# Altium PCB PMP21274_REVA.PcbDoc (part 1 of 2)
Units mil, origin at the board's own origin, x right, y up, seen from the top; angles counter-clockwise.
Board outline 3250 x 2700 mil, 4 copper layers (Top Layer, Signal Layer 1, Signal Layer 2, Bottom Layer), stack 61.6 mil thick; 81 components, 30 nets, 178 pads, 45 vias.
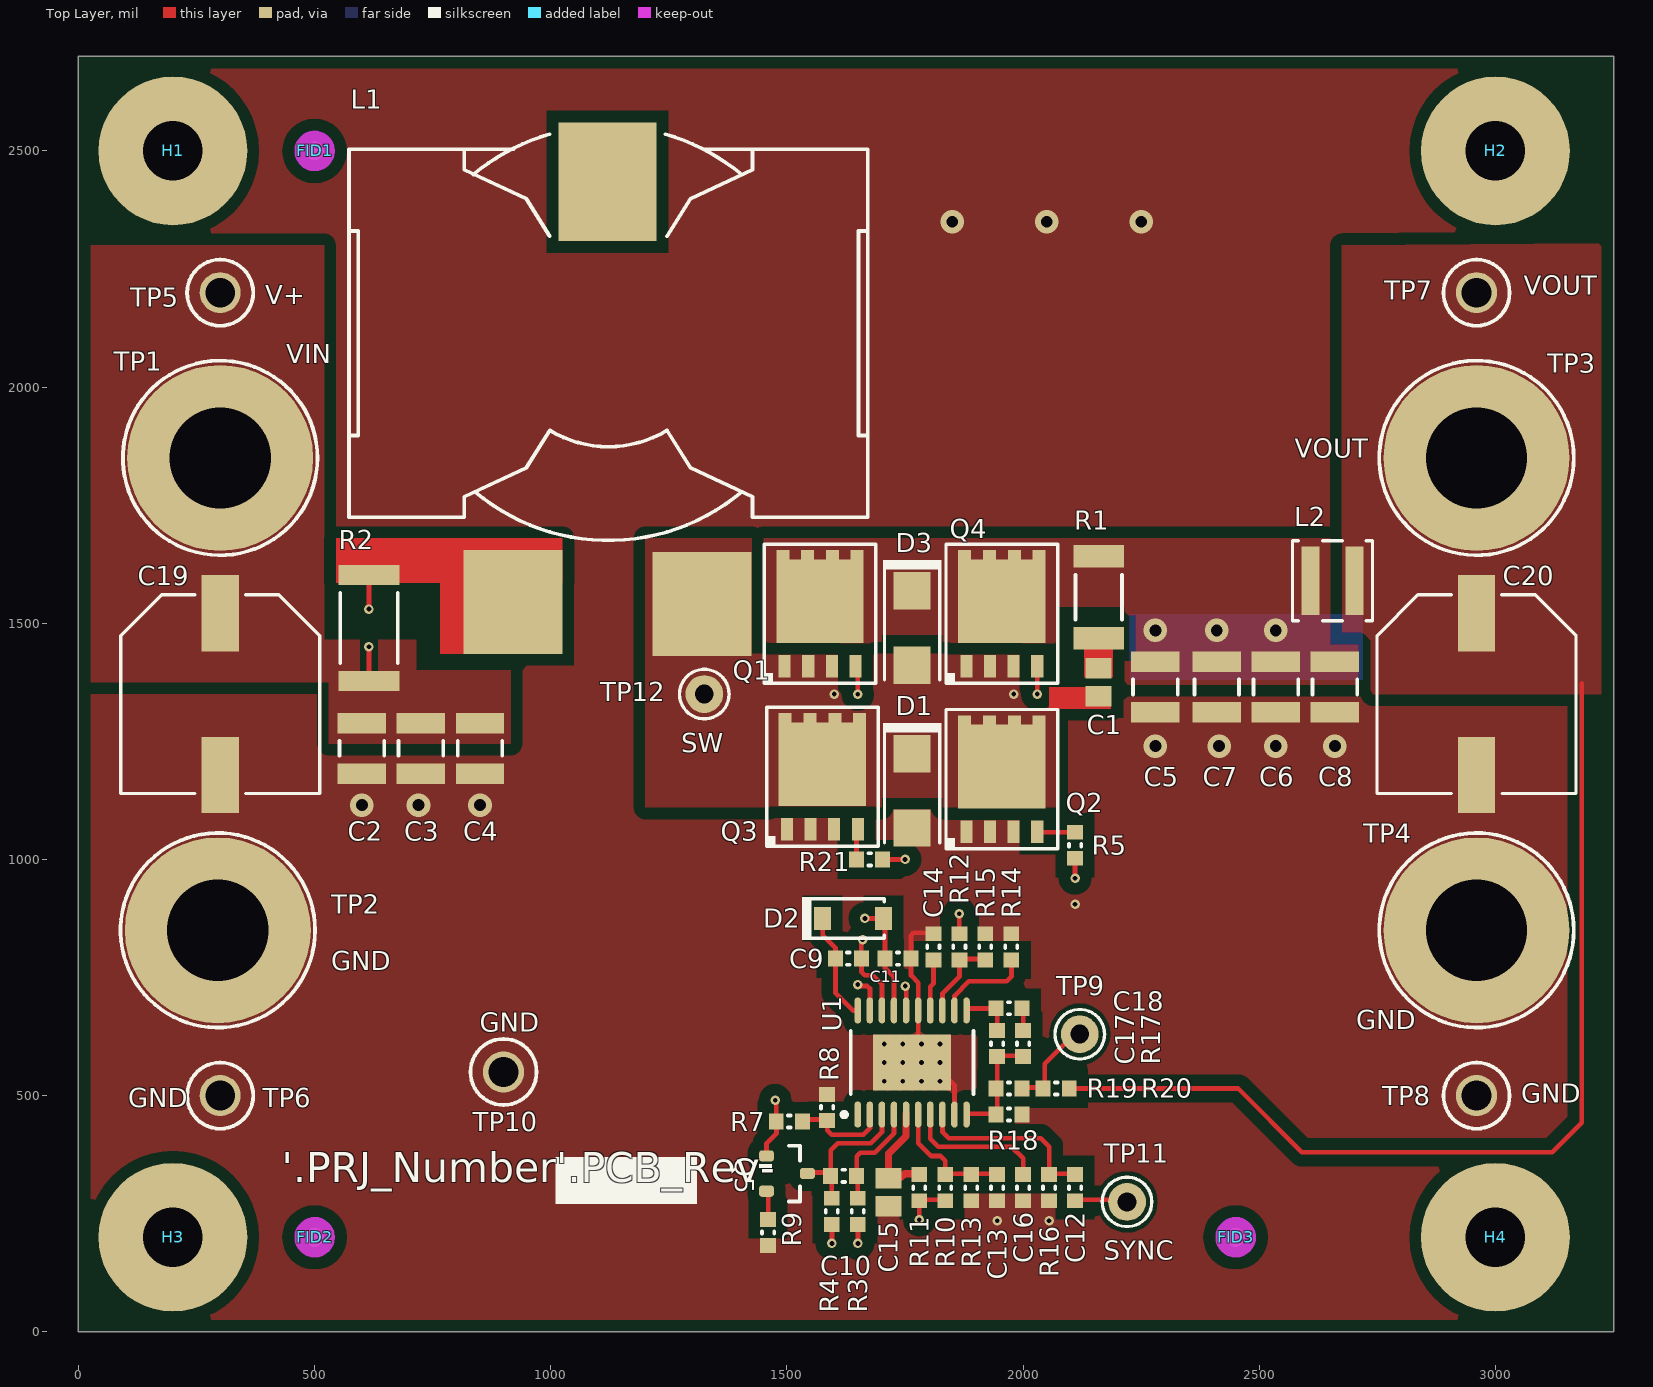
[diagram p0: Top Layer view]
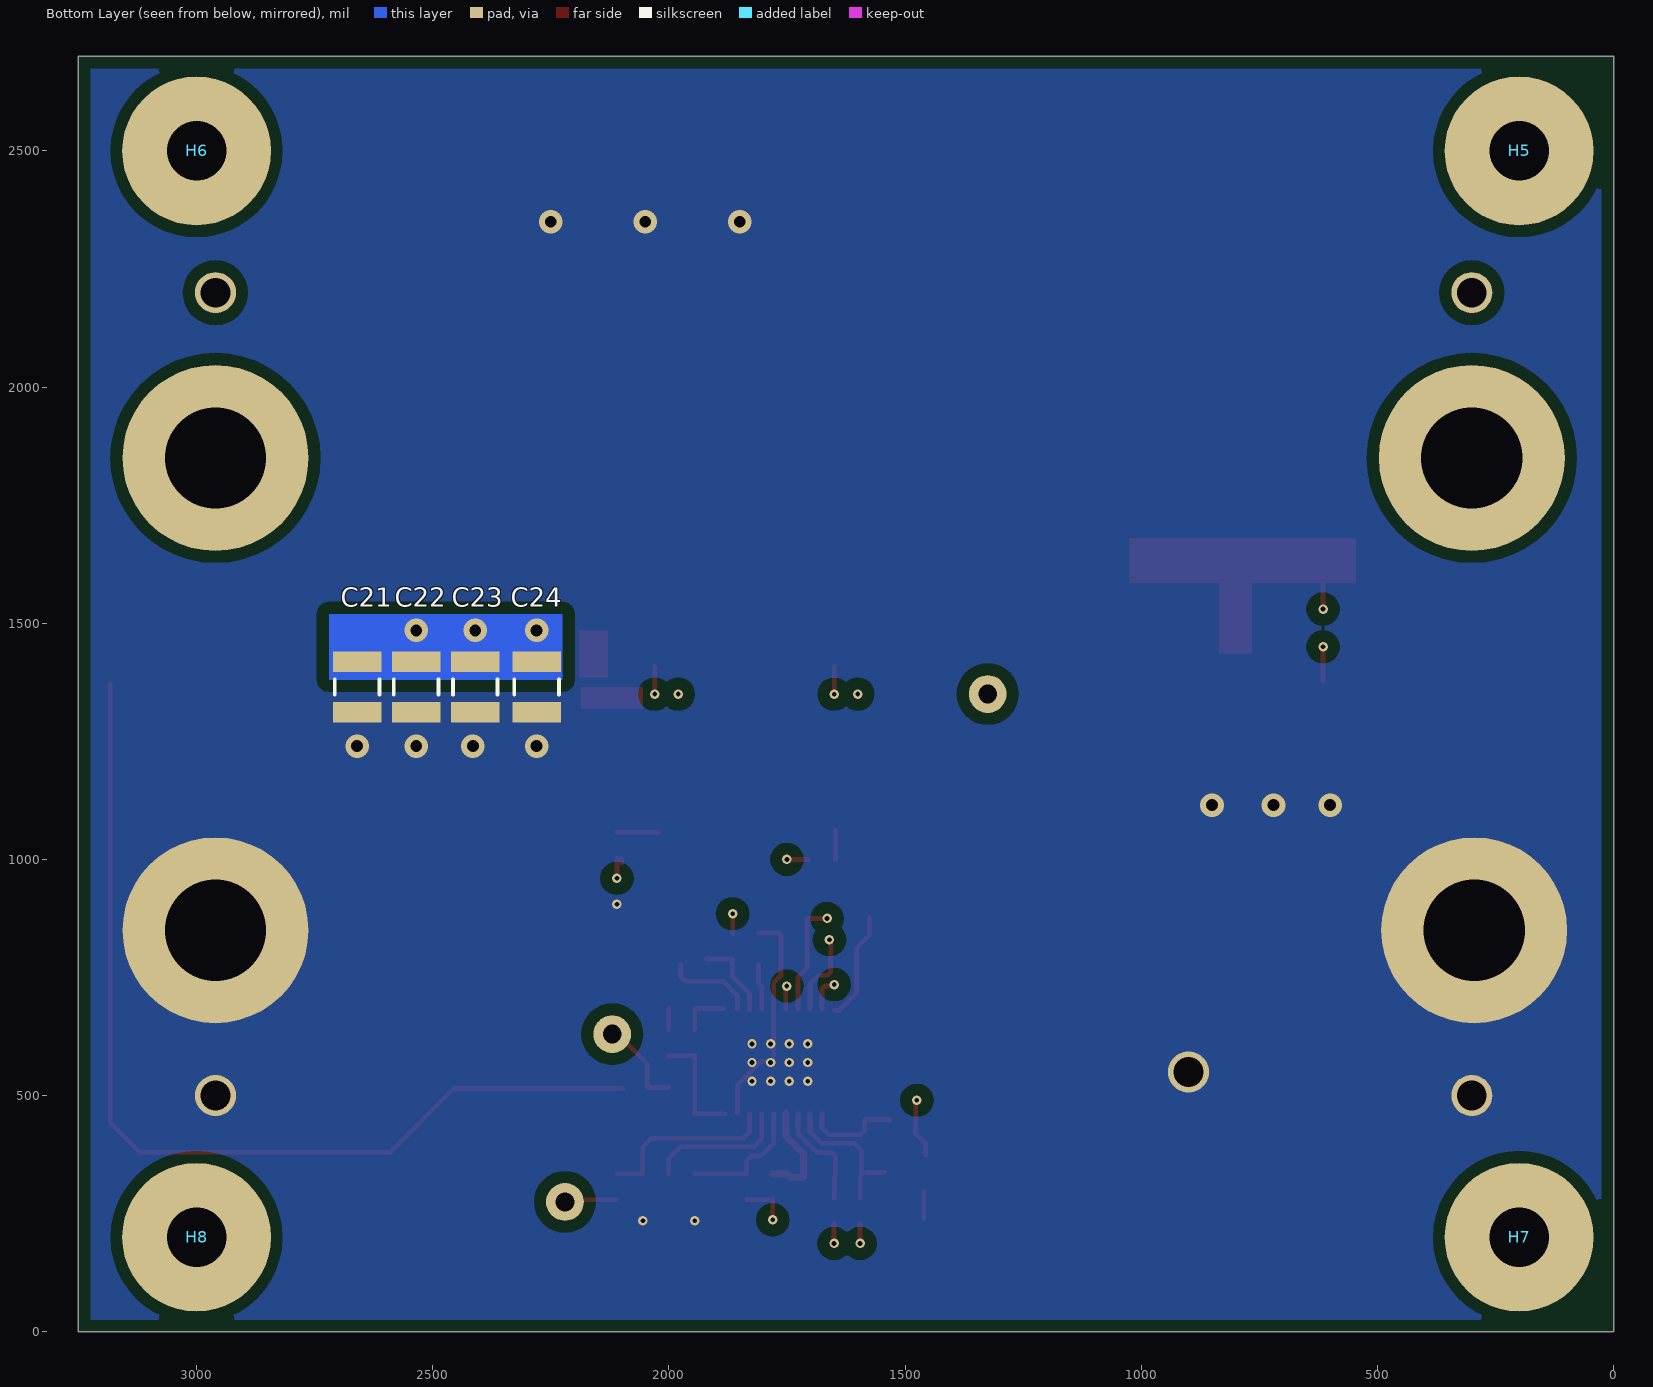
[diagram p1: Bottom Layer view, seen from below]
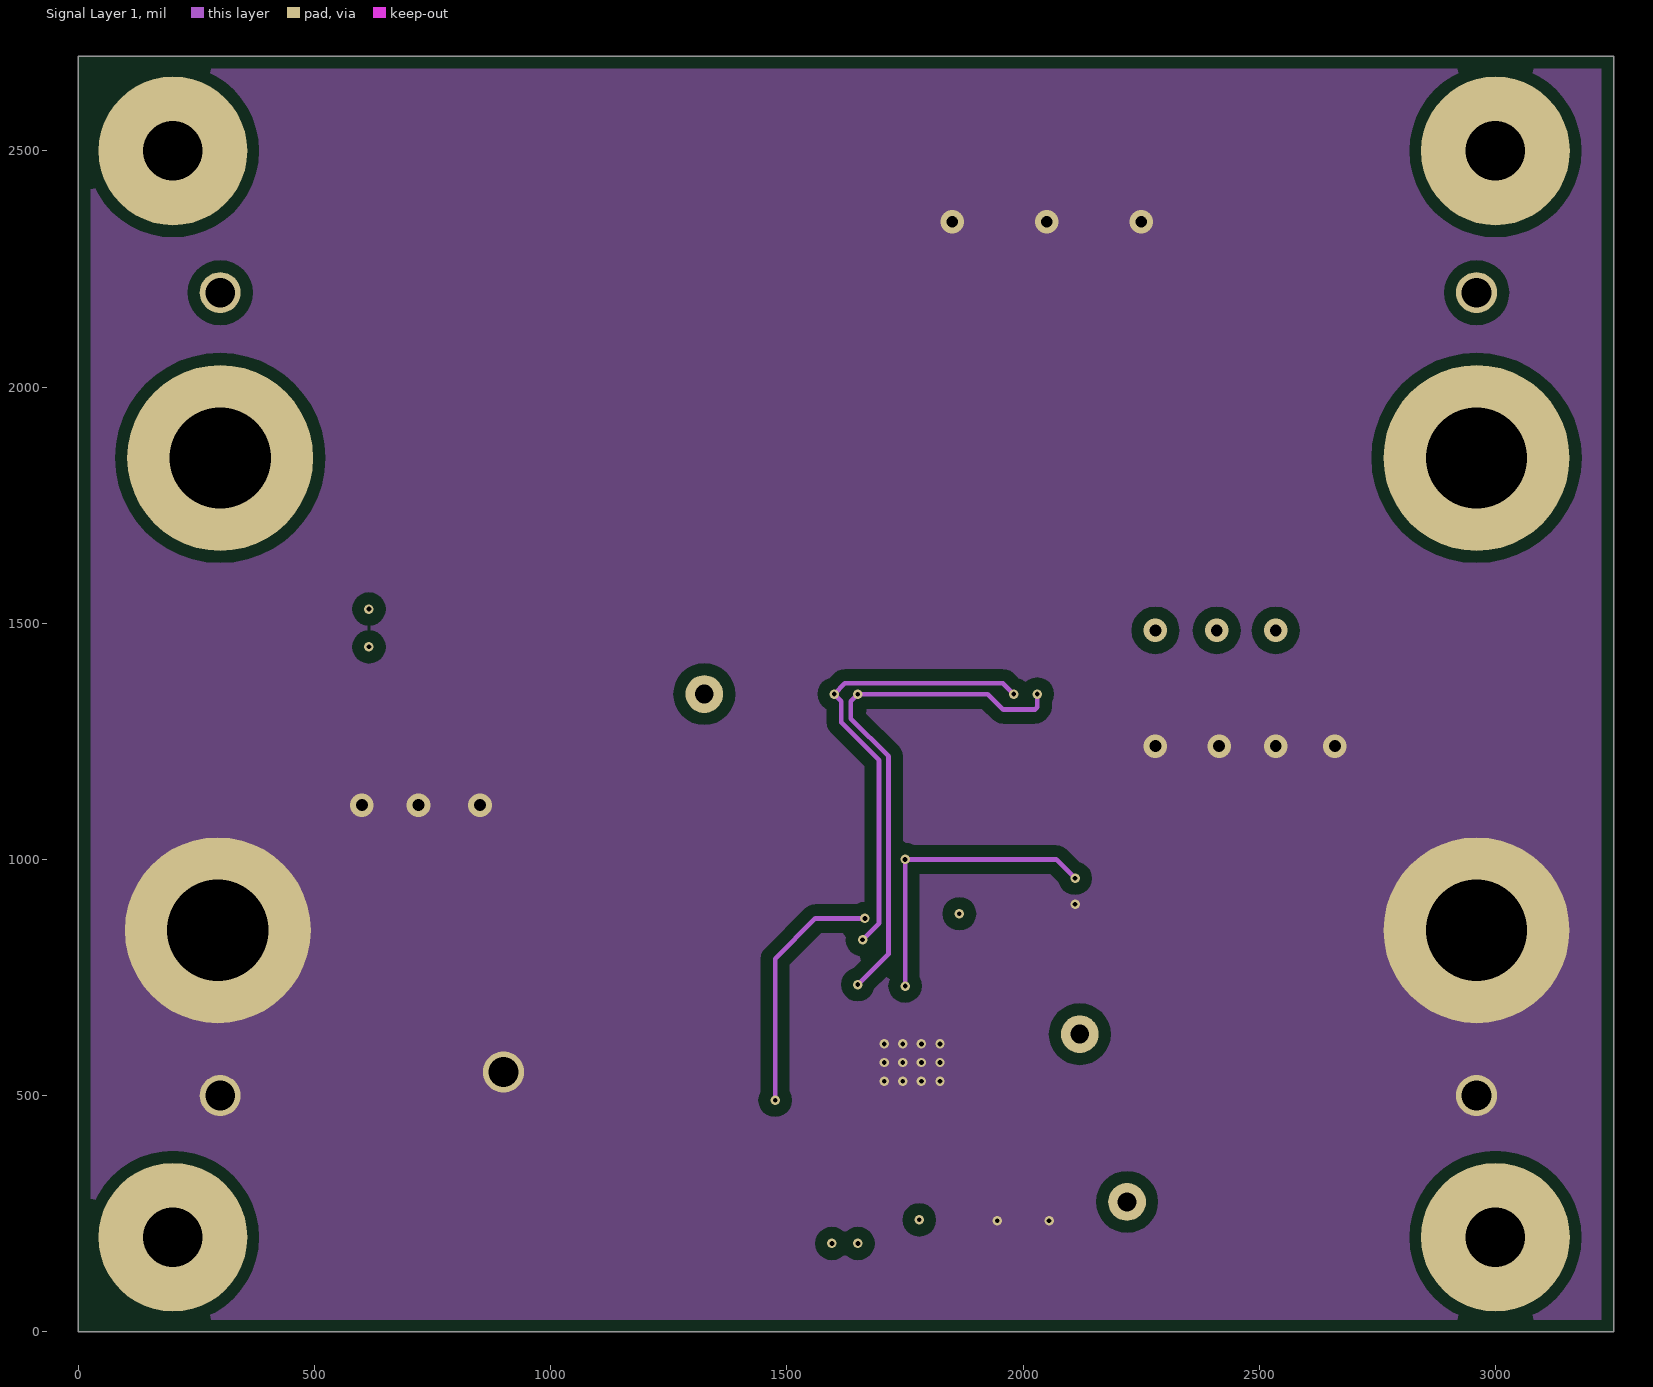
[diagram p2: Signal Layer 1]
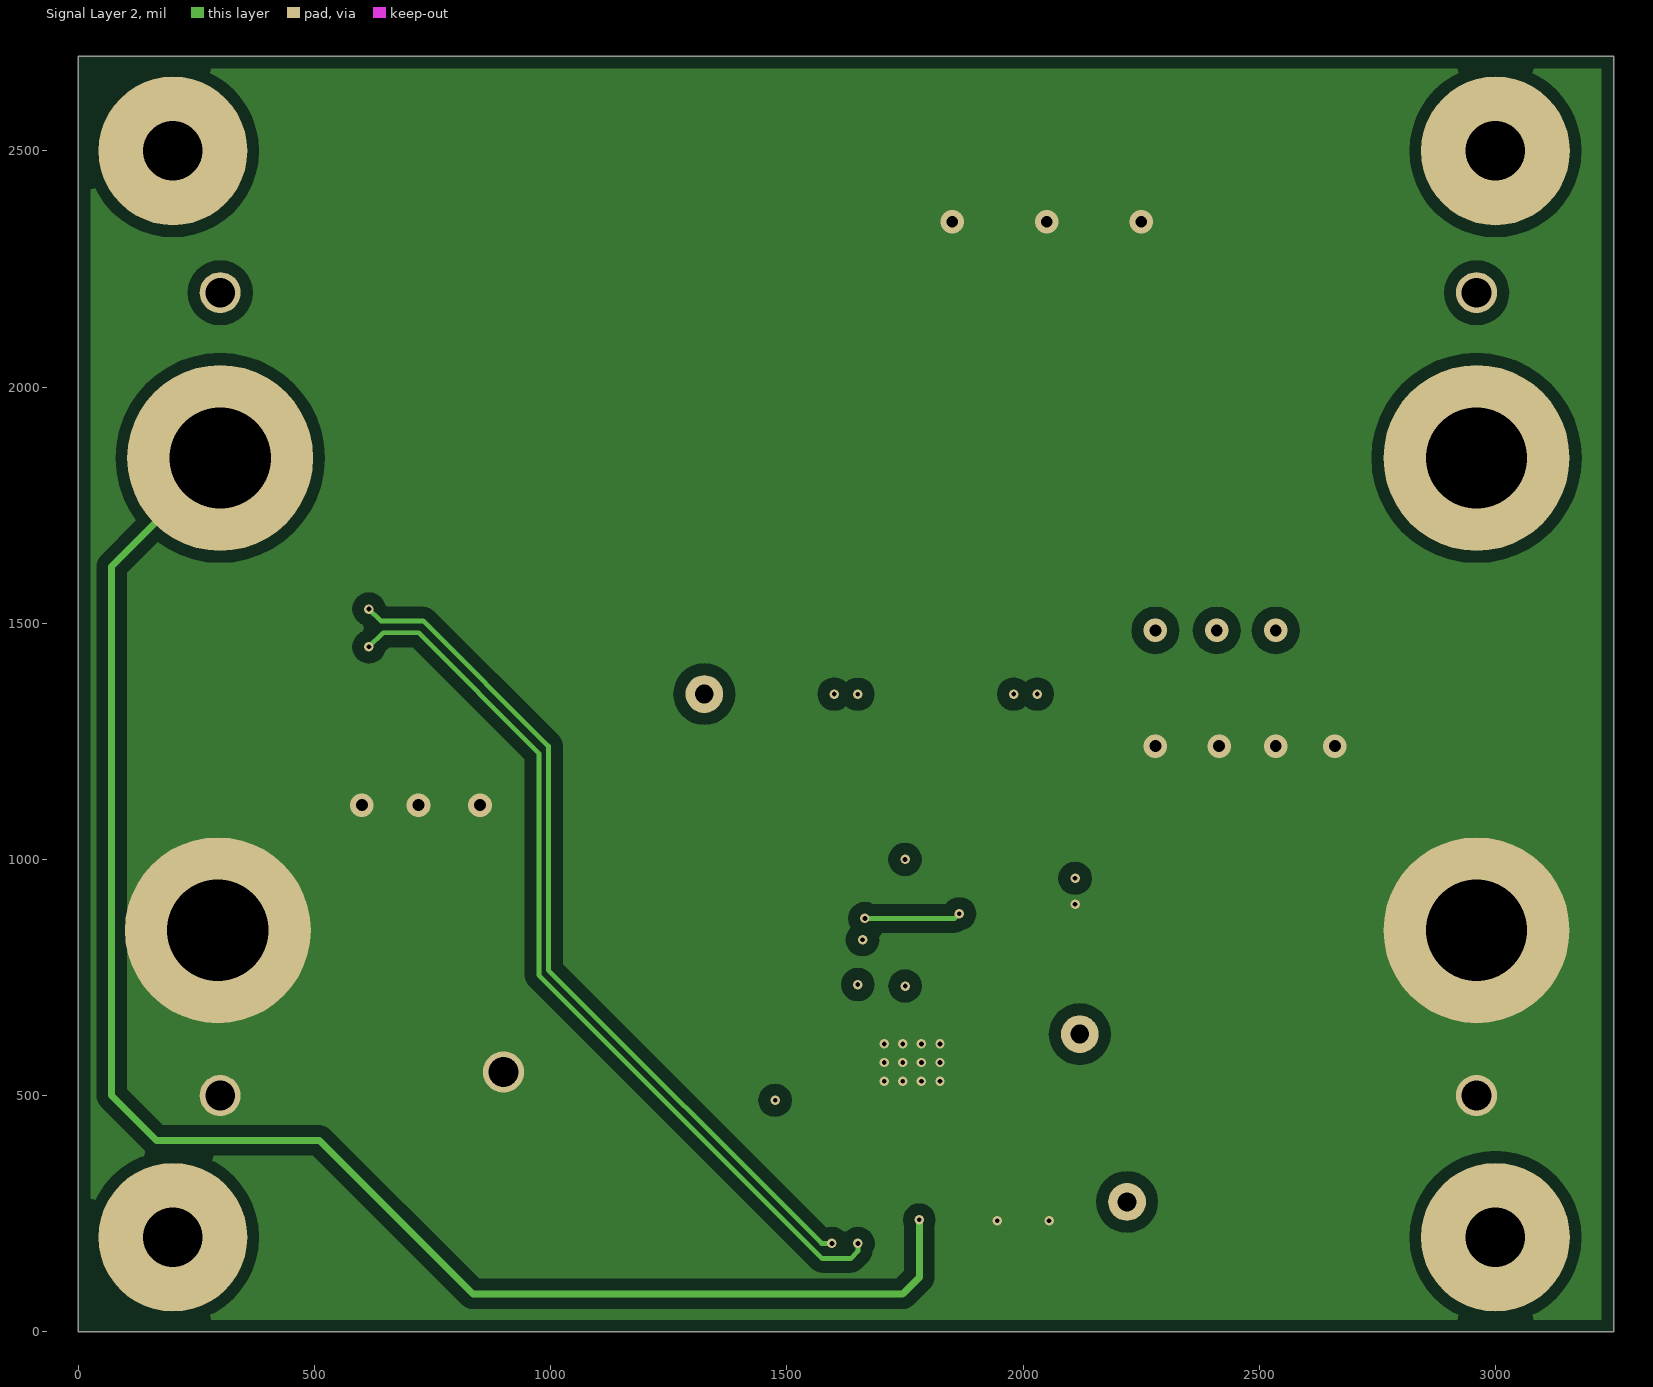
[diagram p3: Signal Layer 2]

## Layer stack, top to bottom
Top Solder: solder mask 0.4, Solder Resist, Dk 3.5
Top Layer: signal copper 1.4
Dielectric1: core 14, FR-4, Dk 4.2
Signal Layer 1: signal copper 1.4
Dielectric 2: core 28, Dk 4.2
Signal Layer 2: signal copper 1.4
Dielectric 3: core 14, Dk 4.2
Bottom Layer: signal copper 1.4
Bottom Solder: solder mask 0.4, Solder Resist, Dk 3.5

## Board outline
0,0 3250,0 3250,2700 0,2700

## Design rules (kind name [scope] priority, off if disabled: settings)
AcuteAngle [All] p1: minimum=4.50000000000000E+0001 checktracksonly=FALSE
AssemblyTestPointUsage [All] p1: valid=2
BoardOutlineClearance BoardOutlineClearance_MountingHoles [OnCopper and InComponentClass('Mounting Holes')] p1: gap=40 ignorepadtopadclearanceinfootprint=FALSE
BoardOutlineClearance BoardOutlineClearance_Poly [OnCopper and IsPoly] p2: gap=25 ignorepadtopadclearanceinfootprint=FALSE
BoardOutlineClearance [OnCopper and Not InComponentClass('Logo') and not InComponentClass('FiducialMark') and not InRegion(1000,500,4000,800) and not InPoly] p3: gap=49 ignorepadtopadclearanceinfootprint=FALSE
Clearance Clearance_Keepouts [((IsTrack Or IsArc) And Not InPoly) And IsFree and IsKeepOut vs ((IsTrack Or IsArc) And Not InPoly) And IsFree and IsKeepOut] p1: gap=0 ignorepadtopadclearanceinfootprint=FALSE
Clearance Clearance_Poly [InPolygon] p2: gap=25 ignorepadtopadclearanceinfootprint=FALSE except(0: Arc-Hole Track-Hole SMDPad-Hole THPad-Hole Via-Hole Fill-Hole Poly-Hole Region-Hole Text-Hole)
Clearance Clearance_FiducialMark [IsKeepOut and InComponentClass('FiducialMark') vs IsPad and InComponentClass('FiducialMark')] p3: gap=0 ignorepadtopadclearanceinfootprint=FALSE
Clearance [All] p4: gap=7.87 ignorepadtopadclearanceinfootprint=FALSE except(0: Arc-Hole Track-Hole SMDPad-Hole THPad-Hole Via-Hole Fill-Hole Poly-Hole Region-Hole Text-Hole)
ComponentClearance ComponentClearance_MountingHoles_FiducialMarks [InComponentClass('Mounting Holes') vs InComponentClass('FiducialMark')] p1: gap=50 collisioncheckmode=3 verticalgap=10 showdistances=FALSE
ComponentClearance ComponentClearance_Shunt [InComponentClass('Header') vs InComponentClass('Shunt')] p2: gap=0 collisioncheckmode=3 verticalgap=0 showdistances=FALSE
ComponentClearance ComponentClearance_Logo [InComponentClass('Logo')] p3: gap=50 collisioncheckmode=3 verticalgap=10 showdistances=FALSE
ComponentClearance ComponentClearance_ScrewToNut [(HasFootprint('NY PMS 440 0025 PH')) vs (HasFootprint('Keystone_1902C'))] p4: gap=5 collisioncheckmode=3 verticalgap=10 showdistances=FALSE
ComponentClearance ComponentClearance_MountingHoles [InComponentClass('Mounting Holes')] p5: gap=100 collisioncheckmode=3 verticalgap=100000 showdistances=FALSE
ComponentClearance ComponentClearance_SmallPassives [HasFootprint('0201*') or HasFootprint('0402*') or HasFootprint('0508') or HasFootprint('0603*') or HasFootprint('0612') or HasFootprint('0805*') or HasFootprint('0815*') or HasFootprint('0830*') or HasFootprint('1206*') or HasFootprint('1210*') or HasFootprint('1808*') or HasFootprint('1812*') or HasFootprint('1825*') or HasFootprint('2010*') or HasFootprint('2220*') or HasFootprint('2225*') or HasFootprint('2512*') or HasFootprint('2728*') or HasFootprint('3518*') vs HasFootprint('0201*') or HasFootprint('0402*') or HasFootprint('0508') or HasFootprint('0603*') or HasFootprint('0612') or HasFootprint('0805*') or HasFootprint('0815*') or HasFootprint('0830*') or HasFootprint('1206*') or HasFootprint('1210*') or HasFootprint('1808*') or HasFootprint('1812*') or HasFootprint('1825*') or HasFootprint('2010*') or HasFootprint('2220*') or HasFootprint('2225*') or HasFootprint('2512*') or HasFootprint('2728*') or HasFootprint('3518*')] p6: gap=14.96 collisioncheckmode=3 verticalgap=10 showdistances=FALSE
ComponentClearance ComponentClearance_THtoSMT [IsThruComponent vs IsSMTComponent] p7: gap=40 collisioncheckmode=3 verticalgap=30 showdistances=FALSE
ComponentClearance ComponentClearance_THtoTH [IsThruComponent vs IsThruComponent] p8: gap=30 collisioncheckmode=3 verticalgap=30 showdistances=FALSE
ComponentClearance [All] p9: gap=30 collisioncheckmode=3 verticalgap=10 showdistances=FALSE
DiffPairsRouting [All] p1: maxlimit=100 minlimit=10 mostfreqgap=10 toplayer_minwidth=10 toplayer_maxwidth=15 toplayer_prefwidth=15 midlayer1_minwidth=10 midlayer1_maxwidth=15 midlayer1_prefwidth=15 midlayer2_minwidth=10 midlayer2_maxwidth=15 midlayer2_prefwidth=15 bottomlayer_minwidth=10 bottomlayer_maxwidth=15 bottomlayer_prefwidth=15 maxuncoupledlength=1000
FabricationTestPointUsage TestPointUsage [All] p1: valid=2 allowmultiple=FALSE
FabricationTestpoint Testpoint [All] p1: side=3 testpointundercomponent=TRUE minsize=40 maxsize=100 preferedsize=60 minholesize=0 maxholesize=40 preferedholesize=32 testpointgrid=1 allowsidetop=TRUE allowsidebottom=TRUE usegrid=TRUE gridtolerance=0.01
FanoutControl Fanout_LCC [IsLCC] p1: bgadir=Out bgaviamode=Centered fanoutstyle=Auto fanoutdirection=Alternating viagrid=1 // Fanout_LCC (Default Rule)
FanoutControl Fanout_BGA [IsBGA] p2: bgadir=Out bgaviamode=Centered fanoutstyle=Auto fanoutdirection=Alternating viagrid=1 // Fanout_BGA (Default Rule)
FanoutControl Fanout_Default [All] p4: bgadir=Out bgaviamode=Centered fanoutstyle=Auto fanoutdirection=Alternating viagrid=1 // Fanout_Default (Default Rule)
FanoutControl Fanout_Small [(CompPinCount < 5)] p5: bgadir=Out bgaviamode=Centered fanoutstyle=Auto fanoutdirection=OutThenIn viagrid=1 // Fanout_Small (Default Rule)
HoleSize [All] p1: absolutevalues=TRUE maxlimit=251 minlimit=7.87 maxpercent=80.000 minpercent=20.000
MinimumAnnularRing MinimumAnnularRing_ThermalPadVias [IsVia and InAnyComponent] p1: minimumring=5
MinimumAnnularRing [All] p2: minimumring=5
MinimumSolderMaskSliver MinimumSolderMaskSliver_Logo [InComponentClass('Logo') vs InComponentClass('Logo')] p1: minsoldermaskwidth=0.7
MinimumSolderMaskSliver [All] p2: minsoldermaskwidth=3.94
PlaneConnect [All] p1: planeconnectstyle=Direct reliefexpansion=10 reliefentries=4 reliefconductorwidth=10 reliefairgap=10
PolygonConnect [All] p1: connectstyle=Direct reliefconductorwidth=10 reliefentries=4 polygonreliefangle="90 Angle" airgapwidth=10
RoutingVias ThermalPadVias [IsVia and InAnyComponent] p1: holewidth=7.87 width=19.68 viastyle="Through Hole" minholewidth=7.87 minwidth=19.68 maxholewidth=12.99 maxwidth=23.62
RoutingVias [All] p2: holewidth=16 width=34 viastyle="Through Hole" minholewidth=7.87 minwidth=20 maxholewidth=40 maxwidth=65
SilkToBoardRegionClearance [Not ((IsComment or IsDesignator) And (Hide <> 'False')) and not InRegion(1000,500,4000,800)] p1:
SilkToSilkClearance SilkToSilkClearance_Pb-FreeLogo [(HasFootprint('Pb-Free_Overlay_Medium') OR HasFootprint('Pb-Free_Overlay_Small')) vs (HasFootprint('Pb-Free_Overlay_Medium') OR HasFootprint('Pb-Free_Overlay_Small'))] p1: silktosilkclearance=0
SilkToSilkClearance [All] p2: silktosilkclearance=4
SilkToSolderMaskClearance SilkToComponentPadClearance [(IsPad or IsFill or IsRegion) and InAnycomponent] p1: minsilkscreentomaskgap=5 clearancetoexposedcopper=TRUE
SilkToSolderMaskClearance "Silk to Solder Mask Opening" [All] p2: minsilkscreentomaskgap=4 clearancetoexposedcopper=FALSE
SolderMaskExpansion [All] p1: expansion=1.97
Width [All] p1: maxlimit=100 minlimit=6 preferedwidth=10 checkconnectedcopper=TRUE
15 further rules are at their usual default settings.

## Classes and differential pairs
component class "Mounting Holes": H1 H2 H3 H4
component class PMP21274_REVA_Hardware: FID1 FID2 FID3 H1 H2 H3 H4 H5 H6 H7 H8 ZZ2 ZZ3 ZZ4
component class FiducialMark: FID1 FID2 FID3
component class AssemblyNote: ZZ2 ZZ3 ZZ4
component class PMP21274_REVA: C1 C2 C3 C4 C5 C6 C7 C8 C9 C10 C11 C12 C13 C14 C15 C16 C17 C18 C19 C20 C21 C22 C23 C24 D1 D2 D3 L1 L2 Q1 Q2 Q3 Q4 Q5 R1 R2 R3 R4 R5 R7 R8 R9 R10 R11 R12 R13 R14 R15 R16 R17 R18 R19 R20 R21 TP1 TP2 TP3 TP4 TP5 TP6 TP7 TP8 TP9 TP10 TP11 TP12 U1
differential pair CSP: +CSP_P -CSP_N
differential pair SW: +SW_P -SW_N

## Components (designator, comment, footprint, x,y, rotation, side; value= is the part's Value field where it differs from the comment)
C1 "GRM2165C2A471JA01D" 0805L 2160,1375 r270 top value=470pF
C2 "GRM32ER71K475KE14L" 1210L 600,1235 r270 top value=4.7uF
C3 "GRM32ER71K475KE14L" 1210L 725,1235 r270 top value=4.7uF
C4 "GRM32ER71K475KE14L" 1210L 850,1235 r270 top value=4.7uF
C5 "GRM32ER71K475KE14L" 1210L 2280,1365 r270 top value=4.7uF
C6 "GRM32ER71K475KE14L" 1210L 2535,1365 r270 top value=4.7uF
C7 "GRM32ER71K475KE14L" 1210L 2410,1365 r270 top value=4.7uF
C8 "GRM32ER71K475KE14L" 1210L 2660,1365 r270 top value=4.7uF
C9 "GRM188R71E104KA01D" 0603L 1630,790 r180 top value=0.1uF
C10 "GRM1885C1H101JA01D" 0603L 1620,330 r0 top value=100pF
C11 "GCM188R71C105KA64D" 0603L 1735,790 r180 top value=1uF
C12 "GRM1885C1H101JA01D" 0603L 2110,305 r270 top value=100pF
C13 "GRM1885C1H101JA01D" 0603L 1945,305 r270 top value=100pF
C14 "GRM188R71E473KA01D" 0603L 1810,815 r90 top value=0.047uF
C15 "GRM21BR72A474KA73L" 0805L 1715,295 r270 top value=0.47uF
C16 "GRM188R71E104KA01D" 0603L 2000,305 r270 top value=0.1uF
C17 "GRM1885C1H152JA01D" 0603L 1945,610 r270 top value=1500pF
C18 "GRM188R71H153KA01D" 0603L 1970,685 r0 top value=0.015uF
C19 "EEE-FK1K470P" SM_RADIAL_G 300,1350 r270 top value=47uF
C20 "EEE-FK1K470P" SM_RADIAL_G 2960,1350 r270 top value=47uF
C21 "DNP" 1210L 2660,1365 r270 bottom value=4.7uF
C22 "DNP" 1210L 2535,1365 r270 bottom value=4.7uF
C23 "DNP" 1210L 2410,1365 r270 bottom value=4.7uF
C24 "DNP" 1210L 2280,1365 r270 bottom value=4.7uF
D1 "DNP" SMA 1765,1145 r270 top value=100V
D2 "MBR1H100SFT3G" SOD-123FL 1640,875 r0 top value=100V
D3 "DNP" SMA 1765,1490 r270 top value=100V
FID1 "Fiducial" Fiducial10-20 500,2500 r0 top
FID2 "Fiducial" Fiducial10-20 500,200 r0 top
FID3 "Fiducial" Fiducial10-20 2450,200 r0 top
H1 "NY PMS 440 0025 PH" "NY PMS 440 0025 PH" 200,2500 r0 top locked
H2 "NY PMS 440 0025 PH" "NY PMS 440 0025 PH" 3000,2500 r0 top locked
H3 "NY PMS 440 0025 PH" "NY PMS 440 0025 PH" 200,200 r0 top locked
H4 "NY PMS 440 0025 PH" "NY PMS 440 0025 PH" 3000,200 r0 top locked
H5 "1902C" Keystone_1902C 200,2500 r180 bottom locked
H6 "1902C" Keystone_1902C 3000,2500 r180 bottom locked
H7 "1902C" Keystone_1902C 200,200 r180 bottom locked
H8 "1902C" Keystone_1902C 3000,200 r180 bottom locked
L1 "SER2915H-103KL" SER2915H 1120,2110 r90 top value=10uH
L2 "XAL4020-102MEB" XAL4020 2655,1590 r0 top value=1uH
Q1 "BSC072N08NS5ATMA1" PG-TDSON-8 1570,1520 r90 top value=80V
Q2 "BSC072N08NS5ATMA1" PG-TDSON-8 1955,1170 r90 top value=80V
Q3 "BSC072N08NS5ATMA1" PG-TDSON-8 1575,1175 r90 top value=80V
Q4 "DNP" PG-TDSON-8 1955,1520 r90 top value=80V
Q5 "DNP" SOT-23L 1500,335 r0 top value="80 V"
R1 "ERJ-12ZYJ7R5U" 2010L 2160,1555 r90 top value=7.5
R2 "ERJ-M1WSF4M0U" 2512L 615,1490 r90 top value=0.004
R3 "ESR03EZPJ101" 0603L 1650,255 r270 top value=100
R4 "ESR03EZPJ101" 0603L 1595,255 r270 top value=100
R5 "ERJ-3GEY0R00V" 0603L 2110,1030 r270 top value=0
R7 "DNP" 0603L 1505,445 r180 top value=0
R8 "ERJ-3GEY0R00V" 0603L 1585,475 r270 top value=0
R9 "DNP" 0603L 1460,210 r90 top value=60.4k
R10 "CRCW060349K9FKEA" 0603L 1835,305 r270 top value=49.9k
R11 "CRCW06033R30JNEA" 0603L 1780,305 r270 top value=3.3
R12 "ERJ-3GEY0R00V" 0603L 1865,815 r90 top value=0
R13 "CRCW06038K45FKEA" 0603L 1890,305 r90 top value=8.45k
R14 "CRCW060330K0JNEA" 0603L 1975,815 r270 top value=30k
R15 "DNP" 0603L 1920,815 r270 top value=0
R16 "CRCW060340K2FKEA" 0603L 2055,305 r90 top value=40.2k
R17 "CRCW060320K5FKEA" 0603L 2000,610 r90 top value=20.5k
R18 "CRCW06031K96FKEA" 0603L 1970,460 r180 top value=1.96k
R19 "CRCW060384K5FKEA" 0603L 1970,515 r0 top value=84.5k
R20 "CRCW060334R8FKEA" 0603L 2070,515 r0 top value=34.8
R21 "ERJ-3GEY0R00V" 0603L 1675,1000 r0 top value=0
TP1 "VIN" Keystone575-8 300,1850 r90 top
TP2 "GND" Keystone575-8 295,850 r90 top
TP3 "VOUT" Keystone575-8 2960,1850 r90 top
TP4 "GND" Keystone575-8 2960,850 r90 top
TP5 "V+" Keystone5010 300,2200 r0 top
TP6 "GND" Keystone5011 300,500 r0 top
TP7 "VOUT" Keystone5010 2960,2200 r0 top
TP8 "GND" Keystone5011 2960,500 r0 top
TP9 "INJ" Keystone5002 2120,630 r90 top
TP10 "GND" Keystone5011 900,550 r0 top
TP11 "SYNC" Keystone5002 2220,275 r90 top
TP12 "SW" Keystone5002 1325,1350 r90 top
U1 "LM5122MHX/NOPB" MXA20A_L 1765,570 r90 top
ZZ2 "This Assembly Note will show in the PcbDoc and associated outputs" AssemblyNote 185,3829.11 r0 top
ZZ3 "This Assembly Note will show in the PcbDoc and associated outputs" AssemblyNote 185,3740.56 r0 top
ZZ4 "This Assembly Note will show in the PcbDoc and associated outputs" AssemblyNote 185,3652 r0 top

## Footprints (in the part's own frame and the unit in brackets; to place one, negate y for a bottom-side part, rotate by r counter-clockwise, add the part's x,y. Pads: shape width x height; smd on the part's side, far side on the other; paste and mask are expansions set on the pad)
0603L [mm] "0603 from SM-752 data"
  rect 0.8x0.85 smd: 1(-0.7,0) 2(0.7,0)
  silkscreen extent -0.07,-0.33 0.07,0.33, body extent -0.87,-0.47 0.87,0.47, height 1
0805L [mm] "0805 from SM-752 data"
  rect 1.1x1.4 smd: 1(-0.75,0) 2(0.75,0)
  body extent -1.1,-0.72 1.1,0.72, height 1.45
1210L [mm] "1210 from SM-752 data"
  rect 1.1x2.6 smd: 1(-1.35,0) 2(1.35,0)
  silkscreen extent -0.4,-1.2 0.4,1.2, body extent -1.7,-1.35 1.7,1.35, height 1.35
2010L [mm]
  rect 1.2x2.7 smd: 1(-2.2,0) 2(2.2,0)
  silkscreen extent -1.2,-1.25 1.2,1.25, body extent -2.73,-1.45 2.73,1.45, height 1.66
2512L [mm] "Chip Resistor, Body 6.3x3.2mm, IPC High Density"
  rect 1.1x3.3 smd: 1(-2.85,0) 2(2.85,0)
  silkscreen extent -1.9,-1.55 1.9,1.55, body extent -3.22,-1.67 3.22,1.67, height 0.71
AssemblyNote [mil] "Assembly Note"
Fiducial10-20 [mm]
  round 1 smd mask+0.5: 1(0,0)
  Top Layer keep-out circle w1.178: c0,0 r0.5
Keystone575-8 [mm] "Banana Jack"
  round 10 hole 5.45: 1(0,0)
  silkscreen extent -5.23,-5.23 5.23,5.23, body extent -3.92,-3.94 3.95,3.94, height 2.36
Keystone5002 [mil] "For Keystone 500x miniature loop terminals"
  round 80 hole 40: 1(0,0)
  silkscreen extent -52,-52 52,52, body extent -49,-49 49,49, height 182
Keystone5010 [mil] "Keystone Multipurpose loops"
  round 87 hole 63: 1(0,0)
  silkscreen extent -70,-70 70,70, body extent -63,-63 63,62, height 319
Keystone5011 [mil] "Keystone Multipurpose loops"
  round 87 hole 63: 1(0,0)
  silkscreen extent -70,-70 70,70, body extent -63,-63 63,62, height 319
Keystone_1902C [mil] "Hex Standoff, 4-40 threaded, nylon"
  body extent -145,-126 146,126, height 501
MXA20A_L [mm] "TSOP, 20-Leads, Body 6.5x4.4mm, Pitch 0.65mm, Exposed Pad, IPC High Density"
  oval 1.4x0.35 smd: 1(-2.8,2.925) 2(-2.8,2.275) 3(-2.8,1.625) 4(-2.8,0.975) 5(-2.8,0.325) 6(-2.8,-0.325) 7(-2.8,-0.975) 8(-2.8,-1.625) 9(-2.8,-2.275) 10(-2.8,-2.925) 11(2.8,-2.925) 12(2.8,-2.275) 13(2.8,-1.625) 14(2.8,-0.975) 15(2.8,-0.325) 16(2.8,0.325) 17(2.8,0.975) 18(2.8,1.625) 19(2.8,2.275) 20(2.8,2.925)
  rect 3x4.2 smd: 21(0,0)
  silkscreen extent -2.92,-3.3 1.7,3.77, body extent -2.25,-3.3 2.25,3.3, height 1.1
"NY PMS 440 0025 PH" [mm] "4-40 nylon screw and mounting hole"
  round 8 hole 3.2: 1(0,0)
  body extent -3.3,-3.3 3.3,3.3, height 2.69
PG-TDSON-8 [mm] "Infineon recommended land pattern"
  rect 1.2x0.65 smd: 1(-2.825,1.905) 2(-2.825,0.635) 3(-2.825,-0.635) 4(-2.825,-1.905)
  rect 0.5x0.7 smd: 5(3.175,-2) 6(3.175,-0.675) 7(3.175,0.675) 8(3.175,2)
  rect 4.5x4.7 smd paste-2.25: 9(0.675,0)
  silkscreen extent -3.74,-3 3.74,3, body extent -3.17,-2.89 3.17,2.9, height 1.1
SER2915H [mm] "COILCRAFT"
  rect 5.59x5.33 smd: 1(-14.355,5.075) 2(-14.455,-5.075)
  rect 6.35x5.28 smd: 3(8.25,0)
  silkscreen extent -11.04,-14 10.81,13.9, body extent -16.7,-14.05 11.22,13.85, height 15.4
SM_RADIAL_G [mm] "10 x 10.2mm:  Panasonic G"
  rect 4.1x2 smd: 1(-4.35,0) 2(4.35,0)
  silkscreen extent -5.35,-5.35 5.35,5.35, body extent -5.25,-5.25 5.25,5.25, height 10.5
SMA [mm] "Molded Diode, 2-Leads, Body 4.3x2.6mm, IPC Medium Density, based on OnSemi component dimensions and land pattern"
  rect 2x2 smd: 1(-2,0) 2(2,0)
  silkscreen extent -3.66,-1.57 2.79,1.57, body extent -2.6,-1.3 2.6,1.3, height 2.42
SOD-123FL [mm] "Copied from SOD-123"
  rect 0.915x1.22 smd: 1(-1.637,0) 2(1.637,0)
  silkscreen extent -2.74,-1.16 1.68,1.16, body extent -1.9,-0.9 1.9,0.9, height 1
SOT-23L [mm] "SOT23, 3-Leads, Body 2.9x1.3mm, Pitch 0.95mm, Lead Span 2.5mm, IPC High Density"
  rrect50% 0.8x0.6 smd: 1(-1.1,0.95) 2(-1.1,-0.95) 3(1.1,0)
  silkscreen extent -1.5,-1.5 0.7,1.5, body extent -1.16,-1.45 1.21,1.45, height 1
XAL4020 [mil] "Coilcraft XAL4020 7/18/12"
  rect 38x146 smd: 1(-46.5,0) 2(46.5,0)
  silkscreen extent -84,-84 84,84, body extent -84,-84 84,84, height 83

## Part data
C1: "CAP, CERM, 470pF, 100V, +/-5%, C0G/NP0, 0805", Alternate Manufacturer=-, Cap_Case=0805, Manufacturer=MuRata, Supplier Part Number 1=490-1611-1-ND, TempCo=C0G/NP0, Tolerance_%=5, Value1=?, Value2=100V, ValueDisplayed=470pF
C2 C3 C4 C5 C6 C7 C8: "CAP, CERM, 4.7 µF, 80 V, +/- 10%, X7R, 1210", Cap_Case=1210, Manufacturer=MuRata, Supplier Part Number 1=490-9972-1-ND, TempCo=X7R, Tolerance_%=10, Value1=Unknown, Value2=80V, ValueDisplayed=4.7µF
C9: "CAP, CERM, 0.1 µF, 25 V,+/- 10%, X7R, 0603", Cap_Case=0603, Manufacturer=MuRata, Supplier Part Number 1=490-1524-1-ND, TempCo=X7R, Tolerance_%=10, Value2=25V, ValueDisplayed=0.1µF
C10 C12 C13: "CAP, CERM, 100pF, 50V, +/-5%, C0G/NP0, 0603", Alternate Manufacturer=-, Cap_Case=0603, Manufacturer=MuRata, Supplier Part Number 1=490-1427-1-ND, TempCo=C0G/NP0, Tolerance_%=5, Value1=?, Value2=50V, ValueDisplayed=100pF
C11: library part CMP-0007136-5, "CAP, CERM, 1 uF, 16 V, +/- 10%, X7R, AEC-Q200 Grade 1, 0603", Cap_Case=0603, Manufacturer=MuRata, Supplier Part Number 1=490-5241-6-ND, TempCo=X7R, Tolerance_%=10%, Value1=Unknown, Value2=16V, ValueDisplayed=1uF
C14: "CAP, CERM, 0.047uF, 25V, +/-10%, X7R, 0603", Alternate Manufacturer=-, Cap_Case=0603, Manufacturer=MuRata, Supplier Part Number 1=490-1522-1-ND, TempCo=X7R, Tolerance_%=10, Value1=?, Value2=25V, ValueDisplayed=0.047µF
C15: "CAP, CERM, 0.47uF, 100V, +/-10%, X7R, 0805", Cap_Case=0805, Manufacturer=MuRata, Supplier Part Number 1=490-3326-1-ND, TempCo=X7R, Tolerance_%=10, Value1=?, Value2=100V, ValueDisplayed=0.47µF
C16: "CAP, CERM, 0.1uF, 25V, +/-10%, X7R, 0603", Alternate Manufacturer=-, Cap_Case=0603, Manufacturer=MuRata, Supplier Part Number 1=490-1524-1-ND, TempCo=X7R, Tolerance_%=10, Value1=?, Value2=25V, ValueDisplayed=0.1µF
C17: library part CMP-0007186-4, "CAP, CERM, 1500 pF, 50 V, +/- 5%, C0G/NP0, 0603", Cap_Case=0603, Manufacturer=MuRata, Supplier Part Number 1=490-1455-1-ND, TempCo=C0G/NP0, Tolerance_%=5%, Value1=Unknown, Value2=50V, ValueDisplayed=1500pF
C18: library part CMP-0007438-4, "CAP, CERM, 0.015 uF, 50 V, +/- 10%, X7R, 0603", Cap_Case=0603, Manufacturer=MuRata, Supplier Part Number 1=490-1514-1-ND, TempCo=X7R, Tolerance_%=10%, Value1=Unknown, Value2=50V, ValueDisplayed=0.015uF
C19 C20: library part CMP-0011200-2, "CAP, AL, 47 uF, 80 V, +/- 20%, 0.7 ohm, AEC-Q200 Grade 2, SMD", Cap_Case=G, Manufacturer=Panasonic, Supplier Part Number 1=PCE3831CT-ND, Tolerance_%=20%, Value1="0.7 ohm", Value2=80V, ValueDisplayed=47uF
C21 C22 C23 C24: library part GRM32ER71K475KE14L, "CAP, CERM, 4.7 µF, 80 V, +/- 10%, X7R, 1210", Cap_Case=1210, Manufacturer=MuRata, Supplier Part Number 1=490-9972-1-ND, TempCo=X7R, Tolerance_%=10, Value1=Unknown, Value2=80V, ValueDisplayed=4.7µF
D1 D3: library part CMP-0028811-1, "Diode, Schottky, 100 V, 2 A, AEC-Q101, SMA", Manufacturer="Fairchild Semiconductor", PartNumber=SSA210, Supplier Part Number 1=SSA210CT-ND, Value1=2A, Value2=0.8V
D2: library part CMP-0028625-1, "Diode, Schottky, 100 V, 1 A, SOD-123FL", Manufacturer="ON Semiconductor", Supplier Part Number 1=MBR1H100SFT3GOSCT-ND, Value1=1A, Value2=0.76V
FID1 FID2 FID3: "Fiducial mark.  There is nothing to buy or mount.", Manufacturer=N/A
H1 H2 H3 H4: "Machine Screw, Round, #4-40 x 1/4, Nylon, Philips panhead", DigiKeyPartNumber=H542-ND, Manufacturer="B&F Fastener Supply"
H5 H6 H7 H8: "Standoff, Hex, 0.5\"L #4-40 Nylon", Manufacturer=Keystone, Supplier Part Number 1=36-1902C-ND
L1: "Inductor, Shielded E Core, Ferrite, 10 µH, 23.4 A, 0.00186 ohm, SMD", Manufacturer=Coilcraft, Value1="0.00186 ohm", Value2=23.4A, ValueDisplayed=10µH
L2: library part CMP-0060983-1, "Inductor, Shielded, Composite, 1 uH, 8.75 A, 0.01 ohm, SMD", Manufacturer=Coilcraft, Supplier Part Number 1=994-XAL4020-102MEB, Value1="0.01 ohm", Value2=8.75A, ValueDisplayed=1uH
Q1 Q2 Q3: library part CMP-0000905-1, "MOSFET, N-CH, 80 V, 74 A, PG-TDSON-8", Alternate Manufacturer=None, Manufacturer="Infineon Technologies", Supplier Part Number 1=BSC072N08NS5ATMA1-ND, Value2="24 nC"
Q4: library part CMP-0000905-1, "MOSFET, N-CH, 80 V, 74 A, PG-TDSON-8", Alternate Manufacturer=None, Manufacturer="Infineon Technologies", PartNumber=BSC072N08NS5ATMA1, Supplier Part Number 1=BSC072N08NS5ATMA1-ND, Value2="24 nC"
Q5: library part CMP-0000416-2, "Transistor, NPN, 80 V, 0.5 A, SOT-23", Manufacturer="Diodes Inc.", PartNumber=MMBTA06-7-F, Supplier Part Number 1=MMBTA06-FDICT-ND, Value1="0.5 A"
R1: library part CMP-0016199-2, "RES, 7.5, 5%, 0.75 W, AEC-Q200 Grade 0, 2010", Manufacturer=Panasonic, Power_W=750mW, Supplier Part Number 1=P7.5WCT-ND, TempCo="600 ppm/C", Tolerance_%=5%, Value2=0.75W, Value_Code=7R50, ValueDisplayed=7.5
R2: library part CMP-0015813-2, "RES, 0.004, 1%, 1 W, 2512", Manufacturer=Panasonic, Power_W=1W, Supplier Part Number 1=P4.0MCT-ND, TempCo="350 ppm/C", Tolerance_%=1%, Value_Code=4L000, ValueDisplayed=0.004
R3 R4: library part CMP-0025882-3, "RES, 100, 5%, 0.25 W, AEC-Q200 Grade 0, 0603", Manufacturer=Rohm, Power_W=250mW, Supplier Part Number 1=RHM100DCT-ND, TempCo="200 ppm/C", Tolerance_%=5%, Value2=0.25W, Value_Code=100R, ValueDisplayed=100
R5 R8 R12 R21: "RES, 0 ohm, 5%, 0.1W, 0603", Alternate Manufacturer=-, Manufacturer=Panasonic, Power_W=0.1, Supplier Part Number 1=P0.0GCT-ND, TempCo="600 ppm/C", Tolerance_%=5, Value1=5%, Value2=0.1W, Value_Code=0000
R7 R15: library part ERJ-3GEY0R00V, "RES, 0 ohm, 5%, 0.1W, 0603", Alternate Manufacturer=-, Manufacturer=Panasonic, Power_W=0.1, Supplier Part Number 1=P0.0GCT-ND, TempCo="600 ppm/C", Tolerance_%=5, Value1=5%, Value2=0.1W, Value_Code=0000
R9: library part CMP-0022532-3, "RES, 60.4 k, 1%, 0.1 W, 0603", Manufacturer=Vishay-Dale, PartNumber=CRCW060360K4FKEA, Power_W=100mW, Supplier Part Number 1=541-60.4KHCT-ND, TempCo="100 ppm/C", Tolerance_%=1%, Value2=0.1W, Value_Code=60k4, ValueDisplayed=60.4k
R10: "RES, 49.9k ohm, 1%, 0.1W, 0603", Alternate Manufacturer=-, Manufacturer=Vishay-Dale, Power_W=0.1, Supplier Part Number 1=541-49.9KHCT-ND, TempCo="100 ppm/C", Tolerance_%=1, Value1=1%, Value2=0.1W, Value_Code=49k9
R11: "RES, 3.3 ohm, 5%, 0.1W, 0603", Alternate Manufacturer=-, Manufacturer=Vishay-Dale, Power_W=0.1, Supplier Part Number 1=541-3.3GCT-ND, TempCo="200 ppm/C", Tolerance_%=5, Value1=5%, Value2=0.1W, Value_Code=3R30
R13: "RES, 8.45 k, 1%, 0.1 W, 0603", Manufacturer=Vishay-Dale, Power_W=0.1, Supplier Part Number 1=541-8.45KHCT-ND, TempCo="100 ppm/C", Tolerance_%=1, Value1=1%, Value2=0.1W, Value_Code=8k45, ValueDisplayed=8.45k
R14: "RES, 30 k, 5%, 0.1 W, 0603", Manufacturer=Vishay-Dale, Power_W=0.1, Supplier Part Number 1=541-30KGCT-ND, TempCo="200 ppm/C", Tolerance_%=5, Value1=5%, Value2=0.1W, Value_Code=30k0, ValueDisplayed=30k
R16: "RES, 40.2k ohm, 1%, 0.1W, 0603", Alternate Manufacturer=-, Manufacturer=Vishay-Dale, Power_W=0.1, Supplier Part Number 1=541-40.2KHCT-ND, TempCo="100 ppm/C", Tolerance_%=1, Value1=1%, Value2=0.1W, Value_Code=40k2
R17: "RES, 20.5 k, 1%, 0.1 W, 0603", Manufacturer=Vishay-Dale, Power_W=0.1, Supplier Part Number 1=541-20.5KHCT-ND, TempCo="100 ppm/C", Tolerance_%=1, Value1=1%, Value2=0.1W, Value_Code=20k5, ValueDisplayed=20.5k
R18: "RES, 1.96k ohm, 1%, 0.1W, 0603", Manufacturer=Vishay-Dale, Power_W=0.1, Supplier Part Number 1=541-1.96KHCT-ND, TempCo="100 ppm/C", Tolerance_%=1, Value1=1%, Value2=0.1W, Value_Code=1k96
R19: "RES, 84.5k ohm, 1%, 0.1W, 0603", Alternate Manufacturer=-, Manufacturer=Vishay-Dale, Power_W=0.1, Supplier Part Number 1=541-84.5KHCT-ND, TempCo="100 ppm/C", Tolerance_%=1, Value1=1%, Value2=0.1W, Value_Code=84k5
R20: "RES, 34.8, 1%, 0.1 W, 0603", Manufacturer=Vishay-Dale, Power_W=0.1, Supplier Part Number 1=541-34.8HCT-ND, TempCo="100 ppm/C", Tolerance_%=1, Value1=1%, Value2=0.1W, Value_Code=34R8, ValueDisplayed=34.8
TP1 TP2 TP3 TP4: library part 575-8, "Standard Banana Jack, Uninsulated, 8.9mm", Manufacturer=Keystone, Supplier Part Number 1=36-575-8-ND
TP5 TP7: library part CMP-0055147-1, "Test Point, Multipurpose, Red, TH", Color=Red, Manufacturer=Keystone, PartNumber=5010, Supplier Part Number 1=36-5010-ND
TP6 TP8 TP10: library part CMP-0055148-1, "Test Point, Multipurpose, Black, TH", Color=Black, Manufacturer=Keystone, PartNumber=5011, Supplier Part Number 1=36-5011-ND
TP9 TP11 TP12: library part CMP-0055139-1, "Test Point, Miniature, White, TH", Color=White, Manufacturer=Keystone, PartNumber=5002, Supplier Part Number 1=36-5002-ND
U1: "Wide Input Synchronous Boost Controller with Multiple Phase Capability, PWP0020A", Alternate Manufacturer="Texas Instruments", Alternate PartNumber=LM5122MHE/NOPB
ZZ2 ZZ3 ZZ4: library part AssemblyNote

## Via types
v1: diameter 20, hole 10, Top Layer to Bottom Layer, 32 vias
v2: diameter 50, hole 25, Top Layer to Bottom Layer, 13 vias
